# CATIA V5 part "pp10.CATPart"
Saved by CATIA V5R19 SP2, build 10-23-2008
Part number: pp10
Bounding box of the stored display mesh (mm): x -20 to 20, y -147.901 to -75.027, z -75.923 to 75.923
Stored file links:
  C:\Users\Welcome\Documents\thinkm2\pp10.CATPart
  C:\Users\Welcome\Documents\thinkm2\Brasmeca.CATProduct
  C:\Users\Welcome\Documents\thinkm2\pp8copy.CATPart
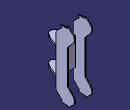
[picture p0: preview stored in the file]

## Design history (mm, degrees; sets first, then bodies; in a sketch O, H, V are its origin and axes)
External parameters (linked from other documents)
  External.Length.1 = 25.952 mm
  External.Length.2 = 15.677 mm
  External.Length.4 = 11.712 mm
  External.Length.3 = 10.679 mm
  External.poche1 = 21 mm
  External.Length.5 = 32.353 mm
AxisSystem1: origin (0, 0, 0), X (1, 0, 0), Y (0, 1, 0), Z (0, 0, 1)
Set1
  Line1: linked copy from another document
  Point1: linked copy from another document
Body1 (main body)
  Plane1: type Offset, RefPlane YZ plane of AxisSystem1, Offset 20
  Plane2: type Normal, Curve Line1, RefPoint Point1
  Sketch1 on Plane1, origin (20, 0, 0), H (0, 1, 0), V (0, 0, 1)
    line L1 (-78.5004, 49.7123) -> (-83.368, 44.0466)
    line L2 (-115.677, 39.6559) -> (-115.677, 49.8573)
    line L3 (-112.0813, 58.3011) -> (-101.9048, 68.0829)
    line L4 (-101.9048, 68.0829) -> (-105.3776, 71.6958)
    line L5 (-105.3776, 71.6958) -> (-89.725, 72.5472)
    line L6 (-89.725, 72.5472) -> (-89.725, 75.9229)
    arc A1 centre (-103.965, 49.8573) radius 11.712 from (-112.0813, 58.3011) to (-115.677, 49.8573) ccw
    line L7 (-78.5004, 49.7123) -> (-78.095, 50.1493)
    arc A2 centre (-86.6815, 58.1144) radius 11.712 from (-78.095, 50.1493) to (-79.1703, 67.1007) ccw
    line L8 (-79.1703, 67.1007) -> (-89.725, 75.9229)
    line L9 (-83.368, 44.0466) -> (-89.725, 37.1937)
    line L10 (-89.725, 37.1937) -> (-89.725, 31.9975)
    reference intersected line E1 through (-100, 0) direction (0, 1) from Plane2
    line L11 (-115.677, -39.6559) -> (-115.677, -49.8573)
    arc A3 centre (-103.965, -49.8573) radius 11.712 from (-112.0813, -58.3011) to (-115.677, -49.8573) cw
    line L12 (-112.0813, -58.3011) -> (-101.9048, -68.0829)
    line L13 (-101.9048, -68.0829) -> (-105.3776, -71.6958)
    line L14 (-105.3776, -71.6958) -> (-89.725, -72.5472)
    line L15 (-89.725, -72.5472) -> (-89.725, -75.9229)
    line L16 (-79.1703, -67.1007) -> (-89.725, -75.9229)
    arc A4 centre (-86.6815, -58.1144) radius 11.712 from (-78.095, -50.1493) to (-79.1703, -67.1007) cw
    line L17 (-78.5004, -49.7123) -> (-83.368, -44.0466)
    line L18 (-83.368, -44.0466) -> (-89.725, -37.1937)
    line L19 (-89.725, -37.1937) -> (-89.725, -31.9975)
    line L20 (-89.725, -31.9975) -> (-89.725, 31.9975)
    line L21 (-115.677, 39.6559) -> (-115.677, -39.6559)
    line L22 (-78.5004, -49.7123) -> (-78.095, -50.1493)
    radius A1 = 11.712 {= External.Length.4}
    radius A2 = 11.712 {= External.Length.4}
    distance L10 L2 = 25.952 {= External.Length.1}
    distance E1 L2 = 15.677 {= External.Length.2}
  Sketch2 on Plane2, origin (0, -100, 0), H (-1, 0, 0), V (0, 0, 1)
    line L1 (-18, 90) -> (-18, 30)
    line L2 (-18, 30) -> (18, 30)
    line L3 (18, 30) -> (18, 90)
    line L4 (18, 90) -> (20, 90)
    line L5 (20, 90) -> (20, -90)
    line L6 (20, -90) -> (18, -90)
    line L7 (18, -90) -> (18, -30)
    line L8 (18, -30) -> (-18, -30)
    line L9 (-18, -30) -> (-18, -90)
    line L10 (-18, -90) -> (-20, -90)
    line L11 (-20, -90) -> (-20, 90)
    line L12 (-18, 90) -> (-20, 90)
    distance L2 H = 30
    distance L8 H = 30
    distance L4 L2 = 60
    distance L8 L6 = 60
    distance L3 V = 18
    distance L5 L11 = 40
    distance L11 V = 20
    distance L12 L2 = 60
    distance L10 L8 = 60
    distance L9 L7 = 36
    distance L7 V = 18
  SolidCombine1: FirstComponentProfile Sketch1, FirstComponentDirection Sketch1, SecondComponentProfile Sketch2, SecondComponentDirection Sketch2
  Sketch3 on face of SolidCombine1 from Sketch1.L20, origin (0, -89.725, 0), H (-1, 0, 0), V (0, 0, 1)
    line L1 (-18, 30) -> (18, 30)
    line L2 (18, 30) -> (18, -30)
    line L3 (18, -30) -> (-18, -30)
    line L4 (-18, -30) -> (-18, 30)
    distance L1 H = 30
    distance L1 L3 = 60
    distance L2 V = 18
    distance L2 L4 = 36
  Pocket1: profile Sketch3, direction (0, -1, 0), length 21 {= External.poche1}
  Sketch4 on face of SolidCombine1 from Sketch2.L8, origin (0, 0, -30), H (1, 0, 0), V (0, -1, 0)
    line L1 (20.0213, 115.677) -> (4.799, 115.677)
    reference projected line E1 (-18, 115.677) -> (18, 115.677) from edge [face of SolidCombine1 from Sketch2.L8 | face of SolidCombine1 from Sketch1.L21]
    line L2 (-20.0213, 115.677) -> (-4.799, 115.677)
    line L3 (4.799, 115.677) -> (-4.799, 115.677)
    distance L1 E1 = 0
    distance L2 E1 = 0
  Sketch5 on face of SolidCombine1 from Sketch2.L2, origin (0, 0, 30), H (1, 0, 0), V (0, 1, 0)
    line L1 (20.0207, -115.6379) -> (-20.1016, -115.6379)
    point P1 (20.0207, -115.6379)
    point P2 (-20.1016, -115.6379)
    spline S1 through (20.0207, -115.6379) (0, -148.03) (-20.1016, -115.6379)
    reference intersected line E1 (20, -115.677) -> (-20, -115.677) from face of SolidCombine1 from Sketch1.L21
    point P3 (20.0207, -115.6379)
    point P4 (-20.1016, -115.6379)
    point P5 (0, -148.03)
    distance P5 E1 = 32.353 {= External.Length.5}
    coincidence: P1 P3, P2 P4
  Sketch6 on face of SolidCombine1 from Sketch1.L21, origin (0, -115.677, 0), H (1, 0, 0), V (0, 0, 1)
    line L1 (-20, 30) -> (20, 30)
    line L2 (20, 30) -> (20, 26)
    line L3 (20, 26) -> (-20, 26)
    line L4 (-20, 26) -> (-20, 30)
    distance L2 V = 20
    distance L2 L4 = 40
    distance L1 H = 30
    distance L3 H = 26
  SolidCombine2: FirstComponentProfile Sketch5, FirstComponentDirection Sketch5, SecondComponentProfile Sketch6, SecondComponentDirection Sketch6
  Mirror1: of SolidCombine2, about XY plane of AxisSystem1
